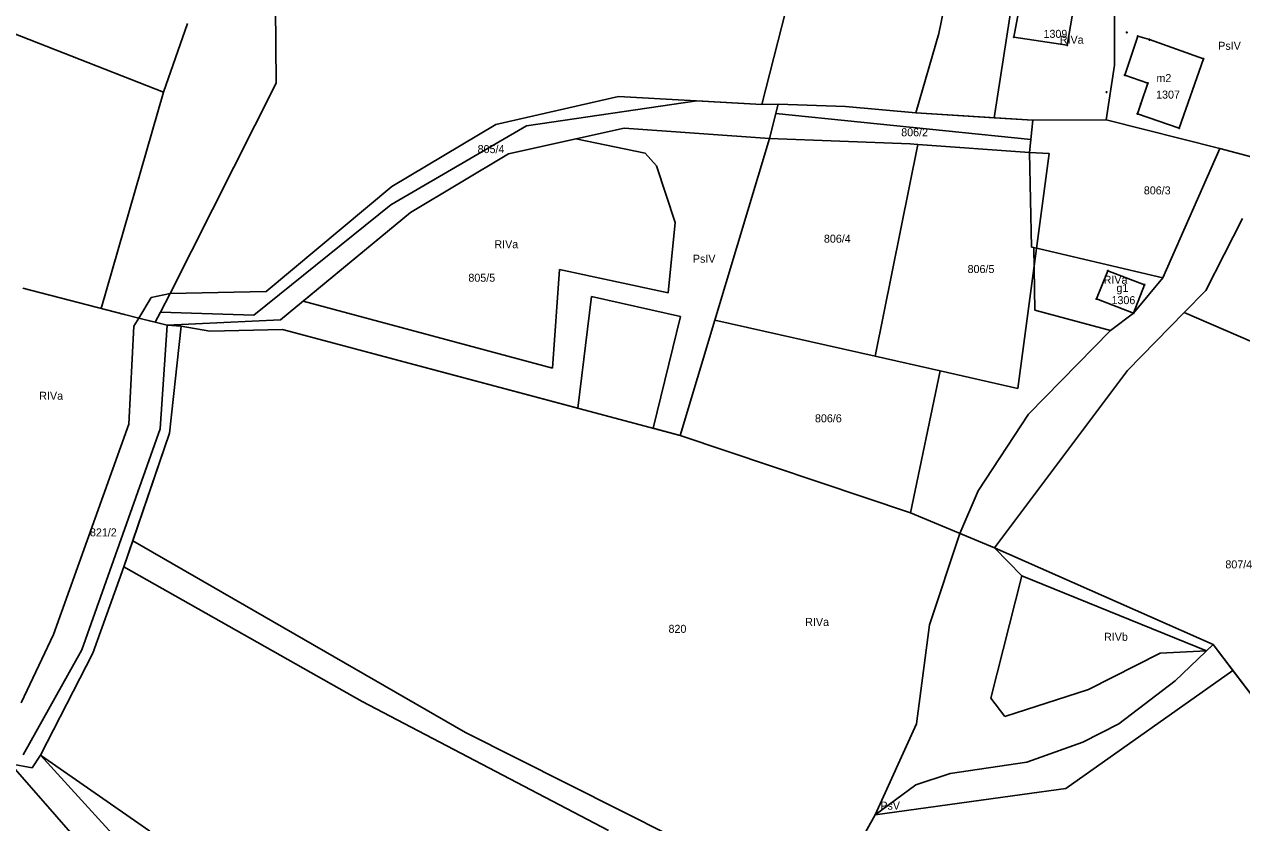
# Model space of a CAD drawing. Extents: x 7498273 to 7499989, y 5499795 to 5500810.
# Drawn here: x 7499540.8 to 7499768.9, y 5500305.7 to 5500455.2 of the extents above; entities that cross this region are included whole.
import ezdxf

# ---------------------------------------------------------------- set-up
doc = ezdxf.new("R2010")
doc.units = 0
for name, color, linetype in [('209-oznaczenie konturu klasyfikacyjnego', 7, 'Continuous'), ('211-numer działki ewidencyjnej', 7, 'Continuous'), ('217-kontur klasyfikacyjny', 7, 'Continuous'), ('218-kontur użytku gruntowego', 7, 'Continuous'), ('219-działka ewidencyjna', 7, 'Continuous'), ('312-budynek ewidencyjny', 7, 'Continuous'), ('312-oznaczenie budynku ewidencyjnego', 7, 'Continuous'), ('312-oznaczenie budynku ewidencyjnego-Atr117', 7, 'Continuous'), ('Punkt budynku', 7, 'Continuous')]:
    doc.layers.add(name, color=color, linetype=linetype)

# ---------------------------------------------------------------- blocks, each defined once
blk = doc.blocks.new('PUNKTBUD')
blk.add_circle((0, 0), 0.09)

msp = doc.modelspace()

# ---------------------------------------------------------------- linework, layer by layer
at = {"layer": '217-kontur klasyfikacyjny'}
for points in [[(7499722.55, 5500437.72), (7499726.6, 5500463.92)], [(7499587.88, 5500458.53), (7499588.02, 5500444.18)], [(7499745.06, 5500447.6), (7499745.1, 5500460.12)], [(7499529.19, 5500457.25), (7499566.88, 5500442.52)], [(7499566.88, 5500442.52), (7499571.38, 5500455.35)], [(7499743.53, 5500437.35), (7499745.06, 5500447.6)], [(7499588.02, 5500444.18), (7499568.15, 5500404.82)], [(7499555.23, 5500402), (7499566.88, 5500442.52)], [(7499634.88, 5500436.22), (7499666.79, 5500440.9)], [(7499666.79, 5500440.9), (7499678.99, 5500440.23)], [(7499678.99, 5500440.23), (7499682.04, 5500440.27)], [(7499682.04, 5500440.27), (7499694.69, 5500439.82)], [(7499681.61, 5500438.54), (7499680.44, 5500433.82)], [(7499729.41, 5500433.65), (7499681.61, 5500438.54)], [(7499694.69, 5500439.82), (7499707.85, 5500438.65)], [(7499707.85, 5500438.65), (7499722.55, 5500437.72)], [(7499609.45, 5500421.41), (7499634.88, 5500436.22)], [(7499722.55, 5500437.72), (7499729.78, 5500437.26)], [(7499729.78, 5500437.26), (7499743.53, 5500437.35)], [(7499764.8, 5500431.96), (7499743.53, 5500437.35)], [(7499644.13, 5500433.77), (7499631.52, 5500430.96)], [(7499657.12, 5500431.07), (7499644.13, 5500433.77)], [(7499680.44, 5500433.82), (7499670.21, 5500399.82)], [(7499729.16, 5500431.23), (7499729.41, 5500433.65)], [(7499729.53, 5500413.49), (7499729.16, 5500431.23)], [(7499754.15, 5500407.76), (7499764.8, 5500431.96)], [(7499774, 5500429.5), (7499764.8, 5500431.96)], [(7499631.52, 5500430.96), (7499613.18, 5500419.96)], [(7499659.23, 5500428.7), (7499657.12, 5500431.07)], [(7499662.74, 5500418.12), (7499659.23, 5500428.7)], [(7499583.82, 5500400.75), (7499609.45, 5500421.41)], [(7499613.18, 5500419.96), (7499593.04, 5500403.38)], [(7499661.44, 5500404.92), (7499662.74, 5500418.12)], [(7499762.17, 5500405.33), (7499769.06, 5500418.86)], [(7499729.93, 5500413.39), (7499729.53, 5500413.49)], [(7499729.93, 5500413.39), (7499730.14, 5500401.67)], [(7499754.15, 5500407.76), (7499729.93, 5500413.39)], [(7499639.8, 5500390.78), (7499641.1, 5500409.29)], [(7499641.1, 5500409.29), (7499661.44, 5500404.92)], [(7499748.65, 5500401.09), (7499754.15, 5500407.76)], [(7499568.15, 5500404.82), (7499566.31, 5500401.29)], [(7499647.1, 5500404.23), (7499644.52, 5500383.31)], [(7499663.74, 5500400.48), (7499647.1, 5500404.23)], [(7499758.11, 5500401.23), (7499762.17, 5500405.33)], [(7499559.59, 5500400.87), (7499555.23, 5500402)], [(7499593.04, 5500403.38), (7499639.8, 5500390.78)], [(7499730.14, 5500401.67), (7499744.31, 5500397.84)], [(7499562.24, 5500400.2), (7499559.59, 5500400.87)], [(7499565.34, 5500399.42), (7499562.24, 5500400.2)], [(7499566.31, 5500401.29), (7499565.34, 5500399.42)], [(7499565.34, 5500399.42), (7499567.57, 5500398.85)], [(7499566.31, 5500401.29), (7499583.82, 5500400.75)], [(7499658.62, 5500379.56), (7499663.74, 5500400.48)], [(7499670.21, 5500399.82), (7499663.71, 5500378.21)], [(7499744.31, 5500397.84), (7499748.65, 5500401.09)], [(7499747.51, 5500390.39), (7499758.11, 5500401.23)], [(7499567.57, 5500398.85), (7499566.28, 5500379.42)], [(7499567.57, 5500398.85), (7499570.2, 5500398.66)], [(7499570.2, 5500398.66), (7499568.03, 5500378.6)], [(7499575.56, 5500397.75), (7499570.2, 5500398.66)], [(7499589.15, 5500398.04), (7499575.56, 5500397.75)], [(7499644.52, 5500383.31), (7499589.15, 5500398.04)], [(7499728.99, 5500382.16), (7499744.31, 5500397.84)], [(7499722.57, 5500357.15), (7499747.51, 5500390.39)], [(7499719.53, 5500367.81), (7499728.99, 5500382.16)], [(7499566.28, 5500379.42), (7499551.56, 5500338.06)], [(7499663.71, 5500378.21), (7499658.62, 5500379.56)], [(7499568.03, 5500378.6), (7499561.12, 5500358.48)], [(7499716.08, 5500359.82), (7499719.53, 5500367.81)], [(7499561.12, 5500358.48), (7499559.44, 5500353.59)], [(7499623.46, 5500322.52), (7499561.12, 5500358.48)], [(7499710.44, 5500342.73), (7499716.08, 5500359.82)], [(7499727.68, 5500351.93), (7499722.57, 5500357.15)], [(7499559.44, 5500353.59), (7499553.67, 5500337.42)], [(7499604.11, 5500328.35), (7499559.44, 5500353.59)], [(7499727.68, 5500351.93), (7499721.89, 5500329.01)], [(7499762.34, 5500337.84), (7499727.68, 5500351.93)], [(7499707.98, 5500324.2), (7499710.44, 5500342.73)], [(7499551.56, 5500338.06), (7499540.6, 5500318.38)], [(7499753.62, 5500337.43), (7499762.34, 5500337.84)], [(7499763.57, 5500339.01), (7499762.34, 5500337.84)], [(7499767.27, 5500334.15), (7499763.57, 5500339.01)], [(7499553.67, 5500337.42), (7499543.84, 5500318.32)], [(7499740.21, 5500330.6), (7499753.62, 5500337.43)], [(7499767.27, 5500334.15), (7499735.94, 5500312.06)], [(7499786.91, 5500308.37), (7499767.27, 5500334.15)], [(7499721.89, 5500329.01), (7499724.52, 5500325.52)], [(7499724.52, 5500325.52), (7499740.21, 5500330.6)], [(7499650.25, 5500304.22), (7499604.11, 5500328.35)], [(7499700.2, 5500307.1), (7499707.98, 5500324.2)], [(7499662.05, 5500303.12), (7499623.46, 5500322.52)], [(7499543.84, 5500318.32), (7499542.28, 5500315.9)], [(7499543.84, 5500318.32), (7499564.29, 5500304.05)], [(7499542.28, 5500315.9), (7499538.24, 5500316.71)], [(7499727.8, 5500310.94), (7499700.2, 5500307.1)], [(7499735.94, 5500312.06), (7499727.8, 5500310.94)]]:
    msp.add_lwpolyline(points, dxfattribs=at)
at = {"layer": '218-kontur użytku gruntowego'}
for points in [[(7499722.55, 5500437.72), (7499726.6, 5500463.92)], [(7499587.88, 5500458.53), (7499588.02, 5500444.18)], [(7499745.06, 5500447.6), (7499745.1, 5500460.12)], [(7499529.19, 5500457.25), (7499566.88, 5500442.52)], [(7499566.88, 5500442.52), (7499571.38, 5500455.35)], [(7499743.53, 5500437.35), (7499745.06, 5500447.6)], [(7499588.02, 5500444.18), (7499568.15, 5500404.82)], [(7499555.23, 5500402), (7499566.88, 5500442.52)], [(7499634.88, 5500436.22), (7499666.79, 5500440.9)], [(7499666.79, 5500440.9), (7499678.99, 5500440.23)], [(7499678.99, 5500440.23), (7499682.04, 5500440.27)], [(7499682.04, 5500440.27), (7499694.69, 5500439.82)], [(7499681.61, 5500438.54), (7499680.44, 5500433.82)], [(7499729.41, 5500433.65), (7499681.61, 5500438.54)], [(7499694.69, 5500439.82), (7499707.85, 5500438.65)], [(7499707.85, 5500438.65), (7499722.55, 5500437.72)], [(7499609.45, 5500421.41), (7499634.88, 5500436.22)], [(7499722.55, 5500437.72), (7499729.78, 5500437.26)], [(7499729.78, 5500437.26), (7499743.53, 5500437.35)], [(7499764.8, 5500431.96), (7499743.53, 5500437.35)], [(7499644.13, 5500433.77), (7499631.52, 5500430.96)], [(7499657.12, 5500431.07), (7499644.13, 5500433.77)], [(7499680.44, 5500433.82), (7499670.21, 5500399.82)], [(7499729.16, 5500431.23), (7499729.41, 5500433.65)], [(7499729.53, 5500413.49), (7499729.16, 5500431.23)], [(7499754.15, 5500407.76), (7499764.8, 5500431.96)], [(7499774, 5500429.5), (7499764.8, 5500431.96)], [(7499631.52, 5500430.96), (7499613.18, 5500419.96)], [(7499659.23, 5500428.7), (7499657.12, 5500431.07)], [(7499662.74, 5500418.12), (7499659.23, 5500428.7)], [(7499583.82, 5500400.75), (7499609.45, 5500421.41)], [(7499613.18, 5500419.96), (7499593.04, 5500403.38)], [(7499661.44, 5500404.92), (7499662.74, 5500418.12)], [(7499762.17, 5500405.33), (7499769.06, 5500418.86)], [(7499729.93, 5500413.39), (7499729.53, 5500413.49)], [(7499729.93, 5500413.39), (7499730.14, 5500401.67)], [(7499754.15, 5500407.76), (7499729.93, 5500413.39)], [(7499639.8, 5500390.78), (7499641.1, 5500409.29)], [(7499641.1, 5500409.29), (7499661.44, 5500404.92)], [(7499748.65, 5500401.09), (7499754.15, 5500407.76)], [(7499568.15, 5500404.82), (7499566.31, 5500401.29)], [(7499647.1, 5500404.23), (7499644.52, 5500383.31)], [(7499663.74, 5500400.48), (7499647.1, 5500404.23)], [(7499758.11, 5500401.23), (7499762.17, 5500405.33)], [(7499559.59, 5500400.87), (7499555.23, 5500402)], [(7499593.04, 5500403.38), (7499639.8, 5500390.78)], [(7499730.14, 5500401.67), (7499744.31, 5500397.84)], [(7499562.24, 5500400.2), (7499559.59, 5500400.87)], [(7499565.34, 5500399.42), (7499562.24, 5500400.2)], [(7499566.31, 5500401.29), (7499565.34, 5500399.42)], [(7499565.34, 5500399.42), (7499567.57, 5500398.85)], [(7499566.31, 5500401.29), (7499583.82, 5500400.75)], [(7499658.62, 5500379.56), (7499663.74, 5500400.48)], [(7499670.21, 5500399.82), (7499663.71, 5500378.21)], [(7499744.31, 5500397.84), (7499748.65, 5500401.09)], [(7499747.51, 5500390.39), (7499758.11, 5500401.23)], [(7499567.57, 5500398.85), (7499566.28, 5500379.42)], [(7499567.57, 5500398.85), (7499570.2, 5500398.66)], [(7499570.2, 5500398.66), (7499568.03, 5500378.6)], [(7499575.56, 5500397.75), (7499570.2, 5500398.66)], [(7499589.15, 5500398.04), (7499575.56, 5500397.75)], [(7499644.52, 5500383.31), (7499589.15, 5500398.04)], [(7499728.99, 5500382.16), (7499744.31, 5500397.84)], [(7499722.57, 5500357.15), (7499747.51, 5500390.39)], [(7499719.53, 5500367.81), (7499728.99, 5500382.16)], [(7499566.28, 5500379.42), (7499551.56, 5500338.06)], [(7499663.71, 5500378.21), (7499658.62, 5500379.56)], [(7499568.03, 5500378.6), (7499561.12, 5500358.48)], [(7499716.08, 5500359.82), (7499719.53, 5500367.81)], [(7499561.12, 5500358.48), (7499559.44, 5500353.59)], [(7499623.46, 5500322.52), (7499561.12, 5500358.48)], [(7499710.44, 5500342.73), (7499716.08, 5500359.82)], [(7499727.68, 5500351.93), (7499722.57, 5500357.15)], [(7499559.44, 5500353.59), (7499553.67, 5500337.42)], [(7499604.11, 5500328.35), (7499559.44, 5500353.59)], [(7499727.68, 5500351.93), (7499721.89, 5500329.01)], [(7499762.34, 5500337.84), (7499727.68, 5500351.93)], [(7499707.98, 5500324.2), (7499710.44, 5500342.73)], [(7499551.56, 5500338.06), (7499540.6, 5500318.38)], [(7499753.62, 5500337.43), (7499762.34, 5500337.84)], [(7499763.57, 5500339.01), (7499762.34, 5500337.84)], [(7499767.27, 5500334.15), (7499763.57, 5500339.01)], [(7499553.67, 5500337.42), (7499543.84, 5500318.32)], [(7499740.21, 5500330.6), (7499753.62, 5500337.43)], [(7499767.27, 5500334.15), (7499735.94, 5500312.06)], [(7499786.91, 5500308.37), (7499767.27, 5500334.15)], [(7499721.89, 5500329.01), (7499724.52, 5500325.52)], [(7499724.52, 5500325.52), (7499740.21, 5500330.6)], [(7499650.25, 5500304.22), (7499604.11, 5500328.35)], [(7499700.2, 5500307.1), (7499707.98, 5500324.2)], [(7499662.05, 5500303.12), (7499623.46, 5500322.52)], [(7499543.84, 5500318.32), (7499542.28, 5500315.9)], [(7499543.84, 5500318.32), (7499564.29, 5500304.05)], [(7499542.28, 5500315.9), (7499538.24, 5500316.71)], [(7499727.8, 5500310.94), (7499700.2, 5500307.1)], [(7499735.94, 5500312.06), (7499727.8, 5500310.94)]]:
    msp.add_lwpolyline(points, dxfattribs=at)
at = {"layer": '219-działka ewidencyjna'}
for points in [[(7499678.99, 5500440.23), (7499687.21, 5500472.56)], [(7499712.18, 5500453.53), (7499714.75, 5500466.36)], [(7499707.85, 5500438.65), (7499712.18, 5500453.53)], [(7499629.17, 5500436.45), (7499652.15, 5500441.7)], [(7499652.15, 5500441.7), (7499678.99, 5500440.23)], [(7499678.99, 5500440.23), (7499682.04, 5500440.27)], [(7499680.44, 5500433.82), (7499682.04, 5500440.27)], [(7499682.04, 5500440.27), (7499694.69, 5500439.82)], [(7499694.69, 5500439.82), (7499707.85, 5500438.65)], [(7499707.85, 5500438.65), (7499729.78, 5500437.26)], [(7499609.66, 5500424.86), (7499629.17, 5500436.45)], [(7499631.52, 5500430.96), (7499653.17, 5500435.78)], [(7499653.17, 5500435.78), (7499680.44, 5500433.82)], [(7499729.16, 5500431.23), (7499729.78, 5500437.26)], [(7499680.44, 5500433.82), (7499670.21, 5500399.82)], [(7499680.44, 5500433.82), (7499706.8, 5500432.82)], [(7499708.23, 5500432.72), (7499700.2, 5500393.06)], [(7499706.8, 5500432.82), (7499708.23, 5500432.72)], [(7499729.16, 5500431.23), (7499708.23, 5500432.72)], [(7499729.16, 5500431.23), (7499732.84, 5500431.03)], [(7499613.18, 5500419.96), (7499631.52, 5500430.96)], [(7499726.98, 5500387.02), (7499732.84, 5500431.03)], [(7499586.09, 5500405.14), (7499609.66, 5500424.86)], [(7499588.78, 5500399.88), (7499613.18, 5500419.96)], [(7499762.17, 5500405.33), (7499769.06, 5500418.86)], [(7499559.59, 5500400.87), (7499540.52, 5500405.82)], [(7499562.24, 5500400.2), (7499564.57, 5500404.06)], [(7499564.57, 5500404.06), (7499568.15, 5500404.82)], [(7499568.15, 5500404.82), (7499586.09, 5500405.14)], [(7499758.11, 5500401.23), (7499762.17, 5500405.33)], [(7499559.59, 5500400.87), (7499562.24, 5500400.2)], [(7499561.31, 5500398.66), (7499562.24, 5500400.2)], [(7499562.24, 5500400.2), (7499567.57, 5500398.85)], [(7499567.57, 5500398.85), (7499588.78, 5500399.88)], [(7499663.71, 5500378.21), (7499670.21, 5500399.82)], [(7499670.21, 5500399.82), (7499700.2, 5500393.06)], [(7499747.51, 5500390.39), (7499758.11, 5500401.23)], [(7499758.11, 5500401.23), (7499778.39, 5500392.51)], [(7499560.37, 5500380.31), (7499561.31, 5500398.66)], [(7499566.28, 5500379.42), (7499567.57, 5500398.85)], [(7499567.57, 5500398.85), (7499570.2, 5500398.66)], [(7499568.03, 5500378.6), (7499570.2, 5500398.66)], [(7499570.2, 5500398.66), (7499575.56, 5500397.75)], [(7499575.56, 5500397.75), (7499589.15, 5500398.04)], [(7499589.15, 5500398.04), (7499663.71, 5500378.21)], [(7499700.2, 5500393.06), (7499712.41, 5500390.31)], [(7499706.83, 5500363.72), (7499712.41, 5500390.31)], [(7499712.41, 5500390.31), (7499726.98, 5500387.02)], [(7499747.51, 5500390.39), (7499722.57, 5500357.15)], [(7499546.3, 5500340.91), (7499560.37, 5500380.31)], [(7499551.56, 5500338.06), (7499566.28, 5500379.42)], [(7499559.44, 5500353.59), (7499568.03, 5500378.6)], [(7499663.71, 5500378.21), (7499706.83, 5500363.72)], [(7499706.83, 5500363.72), (7499722.57, 5500357.15)], [(7499763.57, 5500339.01), (7499722.57, 5500357.15)], [(7499559.44, 5500353.59), (7499553.67, 5500337.42)], [(7499559.44, 5500353.59), (7499604.11, 5500328.35)], [(7499540.23, 5500328.12), (7499546.3, 5500340.91)], [(7499540.6, 5500318.38), (7499551.56, 5500338.06)], [(7499756.43, 5500332.22), (7499763.57, 5500339.01)], [(7499763.57, 5500339.01), (7499786.91, 5500308.37)], [(7499543.84, 5500318.32), (7499553.67, 5500337.42)], [(7499745.91, 5500324.17), (7499756.43, 5500332.22)], [(7499650.25, 5500304.22), (7499604.11, 5500328.35)], [(7499739.16, 5500320.75), (7499745.91, 5500324.17)], [(7499728.66, 5500316.97), (7499739.16, 5500320.75)], [(7499542.28, 5500315.9), (7499543.84, 5500318.32)], [(7499543.84, 5500318.32), (7499569.45, 5500290.17)], [(7499543.84, 5500318.32), (7499564.29, 5500304.05)], [(7499538.24, 5500316.71), (7499564.26, 5500286.9)], [(7499538.24, 5500316.71), (7499542.28, 5500315.9)], [(7499714.27, 5500314.87), (7499707.85, 5500312.77)], [(7499714.27, 5500314.87), (7499728.66, 5500316.97)], [(7499700.2, 5500307.1), (7499707.85, 5500312.77)], [(7499688.83, 5500286.77), (7499700.2, 5500307.1)]]:
    msp.add_lwpolyline(points, dxfattribs=at)
at = {"layer": '312-budynek ewidencyjny'}
for points in [[(7499726.24, 5500452.83), (7499727.58, 5500460.22)], [(7499737.14, 5500456.74), (7499736.23, 5500451.3)], [(7499736.23, 5500451.3), (7499726.24, 5500452.83)], [(7499746.98, 5500445.71), (7499749.44, 5500453)], [(7499749.44, 5500453), (7499751.63, 5500452.35)], [(7499751.63, 5500452.35), (7499761.72, 5500448.76)], [(7499761.72, 5500448.76), (7499757.18, 5500435.79)], [(7499751.33, 5500444.18), (7499746.98, 5500445.71)], [(7499750.02, 5500440.35), (7499751.33, 5500444.18)], [(7499749.37, 5500438.46), (7499750.02, 5500440.35)], [(7499757.18, 5500435.79), (7499749.37, 5500438.46)], [(7499741.7, 5500403.77), (7499743.84, 5500409.07)], [(7499743.84, 5500409.07), (7499750.71, 5500406.42)], [(7499750.71, 5500406.42), (7499748.65, 5500401.09)], [(7499748.65, 5500401.09), (7499741.7, 5500403.77)]]:
    msp.add_lwpolyline(points, dxfattribs=at)

# ---------------------------------------------------------------- block references
at = {"layer": 'Punkt budynku'}
for p in [(7499726.24, 5500452.83), (7499747.36, 5500453.7), (7499749.44, 5500453), (7499751.63, 5500452.35), (7499736.23, 5500451.3), (7499761.72, 5500448.76), (7499746.98, 5500445.71), (7499743.58, 5500442.52), (7499751.33, 5500444.18), (7499750.02, 5500440.35), (7499749.37, 5500438.46), (7499757.18, 5500435.79), (7499743.84, 5500409.07), (7499750.71, 5500406.42), (7499741.7, 5500403.77), (7499748.65, 5500401.09)]:
    msp.add_blockref('PUNKTBUD', p, dxfattribs=at)

# ---------------------------------------------------------------- texts
at = {"layer": '209-oznaczenie konturu klasyfikacyjnego'}
for s, p in [('RIVa', (7499734.83, 5500451.59)), ('PsIV', (7499764.51, 5500450.45)), ('RIVa', (7499628.89, 5500413.28)), ('PsIV', (7499666.07, 5500410.56)), ('RIVa', (7499743.04, 5500406.62)), ('RIVa', (7499543.6, 5500384.89)), ('RIVa', (7499687.12, 5500342.51)), ('RIVb', (7499743.12, 5500339.73)), ('PsV', (7499701.2, 5500308.1))]:
    msp.add_text(s, height=1.5, dxfattribs=at).set_placement(p)
at = {"layer": '211-numer działki ewidencyjnej'}
for s, p in [('806/2', (7499705.11, 5500434.25)), ('805/4', (7499625.74, 5500431.1)), ('806/3', (7499750.57, 5500423.36)), ('806/4', (7499690.63, 5500414.31)), ('805/5', (7499624.01, 5500407)), ('806/5', (7499717.55, 5500408.63)), ('806/6', (7499688.95, 5500380.66)), ('821/2', (7499553.1, 5500359.29)), ('807/4', (7499765.85, 5500353.3)), ('820', (7499661.51, 5500341.22))]:
    msp.add_text(s, height=1.5, dxfattribs=at).set_placement(p)
at = {"layer": '312-oznaczenie budynku ewidencyjnego'}
for s, p in [('1309', (7499731.77, 5500452.69)), ('1307', (7499752.87, 5500441.31)), ('1306', (7499744.51, 5500402.8))]:
    msp.add_text(s, height=1.5, dxfattribs=at).set_placement(p)
at = {"layer": '312-oznaczenie budynku ewidencyjnego-Atr117'}
for s, p in [('m2', (7499752.936, 5500444.4)), ('g1', (7499745.439, 5500405.08))]:
    msp.add_text(s, height=1.5, dxfattribs=at).set_placement(p)

doc.saveas('drawing.dxf')
